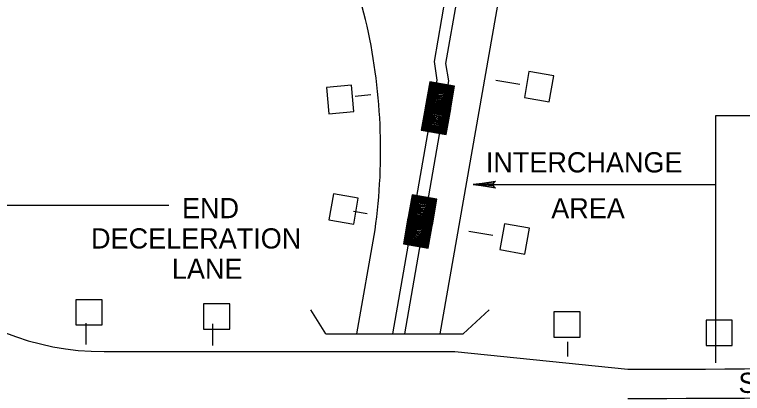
# Model space of a CAD drawing. Extents: x 640253 to 641999, y 298458 to 299646.
# Drawn here: x 641527.8 to 641635.9, y 299419 to 299475.2 of the extents above; entities that cross this region are included whole.
import ezdxf

# ---------------------------------------------------------------- set-up
doc = ezdxf.new("R2010")
doc.units = 0
doc.layers.add('2', color=7, linetype='Continuous')

msp = doc.modelspace()

# ---------------------------------------------------------------- linework, layer by layer
at = {"layer": '2'}
for p, q in [((641591, 299427.89), (641610.58, 299539.79)), ((641590.13, 299468.28), (641594.87, 299495.41)), ((641591.85, 299467.98), (641596.59, 299495.11)), ((641590.55, 299465.5), (641590.13, 299468.28)), ((641592.28, 299465.43), (641591.85, 299467.98)), ((641583.95, 299427.89), (641590.55, 299465.5)), ((641585.72, 299427.89), (641592.28, 299465.43)), ((641599.23, 299465.53), (641602.82, 299464.94)), ((641580.72, 299463.33), (641578.35, 299463.09)), ((641588.79, 299461.56), (641592.39, 299460.97)), ((641631.93, 299424.45), (641631.93, 299460.29)), ((641631.93, 299460.29), (641646.8, 299460.29)), ((641595.89, 299450.02), (641631.93, 299450.02)), ((641526.12, 299446.98), (641550.71, 299446.98)), ((641580.15, 299445.68), (641578.1, 299446.02)), ((641586.23, 299444.88), (641589.82, 299444.29)), ((641578.64, 299427.89), (641581.33, 299443.28)), ((641581.33, 299443.28), (641581.33, 299443.28)), ((641595.23, 299443.11), (641598.83, 299442.52)), ((641574.01, 299427.89), (641571.77, 299431.41)), ((641594.4, 299427.89), (641598.24, 299431.41)), ((641538.42, 299426.26), (641538.42, 299429.45)), ((641557.24, 299426.13), (641557.24, 299429.33)), ((641574.01, 299427.89), (641594.4, 299427.89)), ((641609.94, 299424.48), (641609.94, 299426.69)), ((641541.11, 299425.23), (641541.11, 299425.23)), ((641541.11, 299425.23), (641593.19, 299425.23)), ((641593.19, 299425.23), (641618.86, 299422.63)), ((641593.19, 299425.23), (641593.19, 299425.23)), ((641631.89, 299423.56), (641631.89, 299425.77))]:
    msp.add_line(p, q, dxfattribs=at)
for points in [[(641607.19, 299462.32), (641607.86, 299466.16), (641604.17, 299466.8), (641603.5, 299462.96)], [(641578.19, 299460.86), (641577.84, 299464.75), (641574.11, 299464.41), (641574.46, 299460.53)], [(641578.15, 299444.15), (641578.82, 299447.99), (641575.13, 299448.64), (641574.46, 299444.8)], [(641603.56, 299439.71), (641604.23, 299443.55), (641600.54, 299444.2), (641599.87, 299440.36)], [(641536.89, 299429.18), (641540.79, 299429.18), (641540.79, 299432.92), (641536.89, 299432.92)], [(641555.85, 299428.57), (641559.75, 299428.57), (641559.75, 299432.32), (641555.85, 299432.32)], [(641607.88, 299427.36), (641611.78, 299427.36), (641611.78, 299431.11), (641607.88, 299431.11)], [(641630.46, 299426.15), (641634.36, 299426.15), (641634.36, 299429.9), (641630.46, 299429.9)]]:
    msp.add_lwpolyline(points, close=True, dxfattribs=at)
for points in [[(641592.46, 299460.76), (641593.13, 299464.6), (641589.44, 299465.25), (641588.77, 299461.41), (641592.46, 299460.76), (641589.5, 299465.17), (641588.85, 299461.46), (641592.42, 299460.83), (641593.07, 299464.55), (641589.56, 299465.16), (641588.93, 299461.52), (641592.36, 299460.92), (641592.99, 299464.48), (641589.64, 299465.06), (641589.03, 299461.57), (641592.32, 299461), (641592.92, 299464.43), (641589.68, 299464.99), (641589.1, 299461.63), (641592.27, 299461.08), (641592.84, 299464.36), (641589.74, 299464.9), (641589.18, 299461.69), (641592.23, 299461.14), (641592.76, 299464.31), (641589.8, 299464.81), (641589.26, 299461.74), (641592.17, 299461.22), (641592.68, 299464.25), (641589.85, 299464.73), (641589.34, 299461.8), (641592.1, 299461.3), (641592.59, 299464.18), (641589.93, 299464.64), (641589.43, 299461.87), (641592.07, 299461.37), (641592.5, 299464.1), (641589.97, 299464.55), (641589.51, 299461.93), (641592.01, 299461.46), (641592.43, 299464.03), (641590.01, 299464.45), (641589.6, 299462), (641591.99, 299461.54), (641592.34, 299463.95), (641590.07, 299464.34), (641589.71, 299462.07), (641590.78, 299461.83), (641591.94, 299461.63), (641592.25, 299463.89), (641590.15, 299464.23), (641589.83, 299462.13), (641591.88, 299461.73), (641592.17, 299463.82), (641590.21, 299464.13), (641589.94, 299462.22), (641591.81, 299461.85), (641592.08, 299463.7), (641590.32, 299463.99), (641590.07, 299462.33), (641591.7, 299461.99), (641591.95, 299463.58), (641590.4, 299463.83), (641590.22, 299462.46), (641591.61, 299462.15), (641591.61, 299462.15), (641591.79, 299463.46), (641590.52, 299463.67), (641590.37, 299462.58), (641591.51, 299462.31), (641591.63, 299463.33), (641590.65, 299463.51), (641590.53, 299462.69), (641591.39, 299462.5), (641591.48, 299463.2), (641590.74, 299463.3), (641590.69, 299462.83), (641591.28, 299462.71), (641591.31, 299463.05), (641590.87, 299463.12), (641590.82, 299462.98), (641591.17, 299462.9)], [(641591.88, 299457.43), (641592.55, 299461.27), (641588.86, 299461.92), (641588.19, 299458.07), (641591.88, 299457.43), (641588.91, 299461.84), (641588.27, 299458.13), (641591.84, 299457.5), (641592.49, 299461.22), (641588.98, 299461.83), (641588.34, 299458.19), (641591.78, 299457.59), (641592.41, 299461.15), (641589.05, 299461.73), (641588.44, 299458.24), (641591.74, 299457.67), (641592.34, 299461.1), (641589.1, 299461.66), (641588.51, 299458.3), (641591.69, 299457.75), (641592.26, 299461.03), (641589.15, 299461.56), (641588.59, 299458.36), (641591.64, 299457.81), (641592.18, 299460.98), (641589.21, 299461.47), (641588.68, 299458.41), (641591.59, 299457.89), (641592.1, 299460.92), (641589.27, 299461.4), (641588.76, 299458.47), (641591.52, 299457.96), (641592.01, 299460.85), (641589.35, 299461.31), (641588.85, 299458.54), (641591.49, 299458.04), (641591.91, 299460.76), (641589.39, 299461.21), (641588.93, 299458.6), (641591.43, 299458.13), (641591.84, 299460.7), (641589.43, 299461.12), (641589.02, 299458.67), (641591.41, 299458.21), (641591.76, 299460.62), (641589.49, 299461.01), (641589.12, 299458.74), (641590.2, 299458.5), (641591.35, 299458.3), (641591.67, 299460.56), (641589.57, 299460.9), (641589.24, 299458.8), (641591.29, 299458.4), (641591.59, 299460.48), (641589.63, 299460.8), (641589.36, 299458.88), (641591.22, 299458.52), (641591.5, 299460.37), (641589.74, 299460.66), (641589.49, 299459), (641591.12, 299458.66), (641591.37, 299460.25), (641589.82, 299460.5), (641589.64, 299459.13), (641591.03, 299458.81), (641591.03, 299458.82), (641591.21, 299460.13), (641589.94, 299460.34), (641589.79, 299459.25), (641590.93, 299458.98), (641591.04, 299460), (641590.07, 299460.18), (641589.94, 299459.36), (641590.8, 299459.17), (641590.89, 299459.86), (641590.16, 299459.96), (641590.11, 299459.5), (641590.7, 299459.37), (641590.73, 299459.72), (641590.29, 299459.79), (641590.23, 299459.65), (641590.58, 299459.57)], [(641599.05, 299449.62), (641598.93, 299449.84), (641595.89, 299450.02), (641599.05, 299449.62), (641599.21, 299449.48), (641595.89, 299450.02), (641598.93, 299450.17), (641599.04, 299450.4), (641595.89, 299450.02), (641599.21, 299450.54), (641599.04, 299450.4)], [(641589.84, 299444.01), (641590.51, 299447.85), (641586.82, 299448.5), (641586.15, 299444.65), (641589.84, 299444.01), (641586.87, 299448.42), (641586.23, 299444.71), (641589.8, 299444.08), (641590.45, 299447.8), (641586.94, 299448.41), (641586.3, 299444.77), (641589.74, 299444.17), (641590.36, 299447.73), (641587.01, 299448.31), (641586.4, 299444.82), (641589.7, 299444.25), (641590.3, 299447.68), (641587.06, 299448.24), (641586.47, 299444.88), (641589.65, 299444.32), (641590.22, 299447.61), (641587.11, 299448.14), (641586.55, 299444.94), (641589.6, 299444.39), (641590.14, 299447.56), (641587.17, 299448.05), (641586.64, 299444.99), (641589.55, 299444.47), (641590.06, 299447.5), (641587.23, 299447.97), (641586.72, 299445.05), (641589.48, 299444.54), (641589.96, 299447.43), (641587.31, 299447.89), (641586.81, 299445.12), (641589.45, 299444.62), (641589.87, 299447.34), (641587.35, 299447.79), (641586.89, 299445.18), (641589.39, 299444.71), (641589.8, 299447.28), (641587.39, 299447.7), (641586.98, 299445.25), (641589.37, 299444.79), (641589.72, 299447.2), (641587.45, 299447.59), (641587.08, 299445.32), (641588.16, 299445.08), (641589.31, 299444.88), (641589.63, 299447.14), (641587.53, 299447.48), (641587.2, 299445.38), (641589.25, 299444.98), (641589.55, 299447.06), (641587.59, 299447.38), (641587.32, 299445.46), (641589.18, 299445.1), (641589.46, 299446.95), (641587.7, 299447.24), (641587.45, 299445.58), (641589.08, 299445.24), (641589.33, 299446.83), (641587.78, 299447.08), (641587.6, 299445.71), (641588.99, 299445.39), (641588.99, 299445.4), (641589.17, 299446.71), (641587.9, 299446.92), (641587.75, 299445.82), (641588.89, 299445.56), (641589, 299446.58), (641588.03, 299446.76), (641587.9, 299445.94), (641588.76, 299445.75), (641588.85, 299446.44), (641588.12, 299446.54), (641588.07, 299446.08), (641588.66, 299445.95), (641588.69, 299446.3), (641588.25, 299446.37), (641588.19, 299446.23), (641588.54, 299446.15)], [(641589.23, 299440.58), (641589.9, 299444.42), (641586.21, 299445.07), (641585.54, 299441.22), (641589.23, 299440.58), (641586.27, 299444.99), (641585.62, 299441.28), (641589.19, 299440.65), (641589.84, 299444.37), (641586.34, 299444.98), (641585.7, 299441.34), (641589.14, 299440.74), (641589.76, 299444.3), (641586.41, 299444.88), (641585.8, 299441.39), (641589.09, 299440.82), (641589.69, 299444.25), (641586.46, 299444.81), (641585.87, 299441.45), (641589.05, 299440.9), (641589.61, 299444.18), (641586.51, 299444.71), (641585.95, 299441.51), (641589, 299440.96), (641589.53, 299444.13), (641586.57, 299444.62), (641586.03, 299441.56), (641588.95, 299441.04), (641589.45, 299444.07), (641586.63, 299444.55), (641586.11, 299441.62), (641588.88, 299441.11), (641589.36, 299444), (641586.7, 299444.46), (641586.21, 299441.69), (641588.84, 299441.19), (641589.27, 299443.91), (641586.74, 299444.36), (641586.29, 299441.75), (641588.79, 299441.28), (641589.2, 299443.85), (641586.79, 299444.27), (641586.38, 299441.82), (641588.76, 299441.36), (641589.11, 299443.77), (641586.85, 299444.16), (641586.48, 299441.89), (641587.55, 299441.65), (641588.71, 299441.45), (641589.03, 299443.71), (641586.93, 299444.05), (641586.6, 299441.95), (641588.65, 299441.55), (641588.94, 299443.63), (641586.99, 299443.95), (641586.71, 299442.03), (641588.58, 299441.67), (641588.85, 299443.52), (641587.09, 299443.81), (641586.84, 299442.15), (641588.48, 299441.81), (641588.72, 299443.4), (641587.17, 299443.65), (641586.99, 299442.28), (641588.38, 299441.96), (641588.39, 299441.97), (641588.56, 299443.28), (641587.29, 299443.49), (641587.14, 299442.4), (641588.28, 299442.13), (641588.4, 299443.15), (641587.42, 299443.33), (641587.3, 299442.51), (641588.16, 299442.32), (641588.25, 299443.01), (641587.51, 299443.11), (641587.46, 299442.65), (641588.05, 299442.52), (641588.08, 299442.87), (641587.64, 299442.94), (641587.59, 299442.8), (641587.94, 299442.72)]]:
    msp.add_lwpolyline(points, dxfattribs=at)
for centre, radius, start, end in [((641541.11, 299465.15), 43.39, 80.0478, 246.9218), ((641541.11, 299465.15), 39.92, 13.5395, 270), ((641496.48, 299455.1), 85.67, 352.0739, 13.0849), ((641618.76, 301866.5), 2443.88, 270.0023, 274.32557), ((641618.76, 301866.5), 2448.22, 270.0023, 274.31789)]:
    msp.add_arc(centre, radius, start, end, dxfattribs=at)

# ---------------------------------------------------------------- texts
for s, p in [('INTERCHANGE', (641597.77, 299451.82)), ('END', (641552.66, 299445.03)), ('AREA', (641607.48, 299445)), ('DECELERATION', (641539.16, 299440.53)), ('LANE', (641551.17, 299436.03))]:
    msp.add_text(s, height=3, dxfattribs=at).set_placement(p)
msp.add_text('SOUTHBOUND', height=3, rotation=0.7104, dxfattribs=at).set_placement((641635.29, 299419.08))

doc.saveas('drawing.dxf')
